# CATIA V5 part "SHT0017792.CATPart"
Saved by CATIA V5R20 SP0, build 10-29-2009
Part number: 靠背板
Bounding box of the stored display mesh (mm): x 66.46 to 88.565, y -908.278 to -553.278, z 467.581 to 676.982
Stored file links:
  C:\Users\Administrator\Desktop\桌面\安全带不回位靠背数据\靠背骨架\靠背板\bei-ban-20241122.CATPart
  SHT0016092.CATPart

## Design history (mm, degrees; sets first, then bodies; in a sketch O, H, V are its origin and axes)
Body1 (main body)
  DatumPoint1 to DatumPoint4
  Plane1: type 3Points, Element1 DatumPoint1, Element2 DatumPoint2, Element3 vertex of DatumPoint4
  DatumCurve1 to DatumCurve4
  DatumSurface1
  Sketch1 on Plane1, origin (26.4822, 0, -2.4209), H (0, -1, 0), V (0.091, 0, 0.9958)
    line L1 (903.2778, 681.9618) -> (558.2778, 681.9619)
    line L2 (553.2778, 676.9619) -> (553.2777, 476.9619)
    line L3 (558.2777, 471.9619) -> (763.2777, 471.9618)
    line L4 (908.2777, 476.9618) -> (908.2778, 676.9618)
    point P1 (908.2777, 471.9618)
    reference projected line E1 (567.5257, 484.203) -> (729.0014, 484.2029) from edge of DatumCurve1
    reference projected line E2 through (0.0001, 484.962) direction (1, 0) from edge of DatumCurve2
    point P2 (868.2777, 496.9618)
    line L5 (863.2777, 496.9618) -> (773.2777, 496.9618)
    line L6 (768.2777, 491.9618) -> (768.2777, 476.9618)
    line L7 (868.2777, 476.9618) -> (868.2777, 491.9618)
    point P3 (768.2777, 496.9618)
    arc A1 centre (903.2777, 476.9618) radius 5 from (903.2777, 471.9618) to (908.2777, 476.9618) ccw
    line L8 (873.2777, 471.9618) -> (903.2777, 471.9618)
    arc A2 centre (873.2777, 476.9618) radius 5 from (873.2777, 471.9618) to (868.2777, 476.9618) cw
    arc A3 centre (863.2777, 491.9618) radius 5 from (868.2777, 491.9618) to (863.2777, 496.9618) ccw
    arc A4 centre (773.2777, 491.9618) radius 5 from (773.2777, 496.9618) to (768.2777, 491.9618) ccw
    arc A5 centre (763.2777, 476.9618) radius 5 from (763.2777, 471.9618) to (768.2777, 476.9618) ccw
    arc A6 centre (558.2777, 476.9619) radius 5 from (558.2777, 471.9619) to (553.2777, 476.9619) cw
    arc A7 centre (558.2778, 676.9619) radius 5 from (553.2778, 676.9619) to (558.2778, 681.9619) cw
    arc A8 centre (903.2778, 676.9618) radius 5 from (908.2778, 676.9618) to (903.2778, 681.9618) ccw
    distance L3 E2 = 13
    distance L1 L3 = 210
    distance L4 L2 = 355
    distance P1 L7 = 40
    distance L5 L3 = 25
    radius A1 = 5
    radius A2 = 5
    distance P2 P3 = 100
    radius A3 = 5
    radius A4 = 5
    radius A5 = 5
    radius A6 = 5
    radius A7 = 5
    radius A8 = 5
    parallelism: L3 E1
    perpendicularity: L4 L1, L7 L3, L5 L6
    coincidence: L3 P1, L4 P1, L3 L8, L7 P2, L5 P2, L5 P3, L6 P3
    tangency: A1 L3, A1 L4, A2 L8, A2 L7, A3 L7, A3 L5, A4 L5, A4 L6, A5 L3, A5 L6, A6 L3, A6 L2, A7 L2, A7 L1, A8 L4, A8 L1
    fix: L4
  Pad1: profile Sketch1, direction (-0.9958, 0, 0.091), length 3
  Sketch2 on start face of Pad1, origin (26.4822, 0, -2.4209), H (0, 1, 0), V (0.091, 0, 0.9958)
    point P1 (-893.2777, 491.9618)
    line L1 (-893.2777, 491.9618) -> (-892.2777, 491.9618)
    line L2 (-892.2777, 491.9618) -> (-892.2777, 459.0117)
    line L3 (-892.2777, 459.0117) -> (-893.2777, 459.0117)
    line L4 (-893.2777, 459.0117) -> (-893.2777, 491.9618)
    point P2 (-892.2777, 491.9618)
    point P3 (-892.2777, 459.0117)
    point P4 (-893.2777, 459.0117)
    reference projected line E1 (-908.2777, 476.9618) -> (-908.2778, 676.9618) from edge [start face of Pad1 | face of Pad1 from Sketch1.L4]
    reference projected line E2 (-873.2777, 471.9618) -> (-903.2777, 471.9618) from edge [start face of Pad1 | face of Pad1 from Sketch1.L8]
    reference projected line E3 (-873.2777, 471.9618) -> (-903.2777, 471.9618) from edge [start face of Pad1 | face of Pad1 from Sketch1.L8]
    reference projected line E4 (-908.2777, 476.9618) -> (-908.2778, 676.9618) from edge [start face of Pad1 | face of Pad1 from Sketch1.L4]
    construction line L5 (-1014.6411, 576.9617) -> (-436.3154, 576.9619)
    reference projected line E5 (-903.2778, 681.9618) -> (-558.2778, 681.9619) from edge [start face of Pad1 | face of Pad1 from Sketch1.L1]
    reference projected line E6 (-903.2778, 681.9618) -> (-558.2778, 681.9619) from edge [start face of Pad1 | face of Pad1 from Sketch1.L1]
    reference projected line E7 (-903.2778, 681.9618) -> (-558.2778, 681.9619) from edge [start face of Pad1 | face of Pad1 from Sketch1.L1]
    reference projected line E8 (-558.2777, 471.9619) -> (-763.2777, 471.9618) from edge [start face of Pad1 | face of Pad1 from Sketch1.L3]
    construction line L6 (-730.7778, 707.0094) -> (-730.7777, 343.3852)
    reference projected line E9 (-553.2778, 676.9619) -> (-553.2777, 476.9619) from edge [start face of Pad1 | face of Pad1 from Sketch1.L2]
    point P9 (-568.2777, 491.9619)
    point P10 (-568.2777, 459.0118)
    line L7 (-568.2777, 459.0118) -> (-568.2777, 491.9619)
    point P11 (-569.2777, 459.0118)
    line L8 (-569.2777, 459.0118) -> (-568.2777, 459.0118)
    point P12 (-569.2777, 491.9619)
    line L9 (-569.2777, 491.9618) -> (-569.2777, 459.0118)
    line L10 (-568.2777, 491.9619) -> (-569.2777, 491.9619)
    construction line L11 (-818.2777, 534.1031) -> (-818.2777, 448.4452)
    reference projected line E10 (-773.2777, 496.9618) -> (-863.2777, 496.9618) from edge [start face of Pad1 | face of Pad1 from Sketch1.L5]
    reference projected point E11 (-773.2777, 496.9618) from vertex [face of Pad1 from Sketch1.L5 | start face of Pad1 | face of Pad1 from Sketch1.A4]
    point P15 (-744.2777, 459.0118)
    point P16 (-744.2777, 491.9618)
    line L12 (-744.2777, 491.9618) -> (-744.2777, 459.0118)
    point P17 (-743.2777, 491.9618)
    line L13 (-743.2777, 491.9618) -> (-744.2777, 491.9618)
    point P18 (-743.2777, 459.0118)
    line L14 (-743.2777, 459.0118) -> (-743.2777, 491.9618)
    line L15 (-744.2777, 459.0118) -> (-743.2777, 459.0118)
    point P19 (-743.2778, 694.9118)
    point P20 (-744.2778, 694.9118)
    line L16 (-744.2778, 694.9118) -> (-743.2778, 694.9118)
    point P21 (-744.2778, 661.9618)
    line L17 (-744.2778, 661.9618) -> (-744.2778, 694.9118)
    point P22 (-743.2778, 661.9618)
    line L18 (-743.2778, 694.9118) -> (-743.2778, 661.9618)
    line L19 (-743.2778, 661.9618) -> (-744.2778, 661.9618)
    point P23 (-568.2778, 694.9119)
    point P24 (-569.2778, 694.9119)
    line L20 (-569.2778, 694.9119) -> (-568.2778, 694.9119)
    point P25 (-569.2778, 661.9619)
    line L21 (-569.2778, 661.9619) -> (-569.2778, 694.9119)
    point P26 (-568.2778, 661.9619)
    line L22 (-568.2778, 694.9119) -> (-568.2778, 661.9619)
    line L23 (-568.2778, 661.9619) -> (-569.2778, 661.9619)
    line L24 (-728.2777, 491.9618) -> (-727.2777, 491.9618)
    line L25 (-727.2777, 491.9618) -> (-727.2777, 459.0118)
    line L26 (-727.2777, 459.0118) -> (-728.2777, 459.0118)
    line L27 (-728.2777, 459.0118) -> (-728.2777, 491.9618)
    line L28 (-760.2778, 694.8433) -> (-759.2778, 694.8433)
    line L29 (-759.2778, 694.8433) -> (-759.2778, 661.9618)
    line L30 (-759.2778, 661.9618) -> (-760.2778, 661.9618)
    line L31 (-760.2778, 661.9618) -> (-760.2778, 694.8433)
    point P35 (-893.2778, 694.9118)
    point P36 (-892.2778, 694.9118)
    line L32 (-892.2778, 694.9118) -> (-893.2778, 694.9118)
    point P37 (-892.2778, 661.9618)
    line L33 (-892.2778, 661.9618) -> (-892.2778, 694.9118)
    point P38 (-893.2778, 661.9618)
    line L34 (-893.2778, 694.9118) -> (-893.2778, 661.9618)
    line L35 (-893.2778, 661.9618) -> (-892.2778, 661.9618)
    distance L1 E3 = 20
    distance L2 L4 = 1
    distance L4 E4 = 15
    distance E6 L5 = 105
    distance E7 E8 = 210 (reference)
    distance L6 E9 = 177.5
    distance L11 E11 = 45
    distance P17 L27 = 15
    distance L27 L25 = 1
    distance P17 L24 = 0
    distance L31 L29 = 1
    distance L30 P21 = 0
    distance L29 L17 = 15
    parallelism: L4 E1, L1 E2, E5 L5, L30 L28
    perpendicularity: L6 L5, L11 E10
    symmetry: P1 P9 L6, P4 P10 L6, L4 L7 L6, P3 P11 L6, L3 L8 L6, P2 P12 L6, L2 L9 L6, L1 L10 L6, P3 P15 L11, P2 P16 L11, L2 L12 L11, P1 P17 L11, L1 L13 L11, P4 P18 L11, L4 L14 L11, L3 L15 L11, P18 P19 L5, P15 P20 L5, L15 L16 L5, P16 P21 L5, L12 L17 L5, P17 P22 L5, L14 L18 L5, L13 L19 L5, P10 P23 L5, P11 P24 L5, L8 L20 L5, P12 P25 L5, L9 L21 L5, P9 P26 L5, L7 L22 L5, L10 L23 L5, P4 P35 L5, P3 P36 L5, L3 L32 L5, P2 P37 L5, L2 L33 L5, P1 P38 L5, L4 L34 L5, L1 L35 L5
  Pocket1: profile Sketch2, direction (-0.9958, 0, 0.091), length 10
